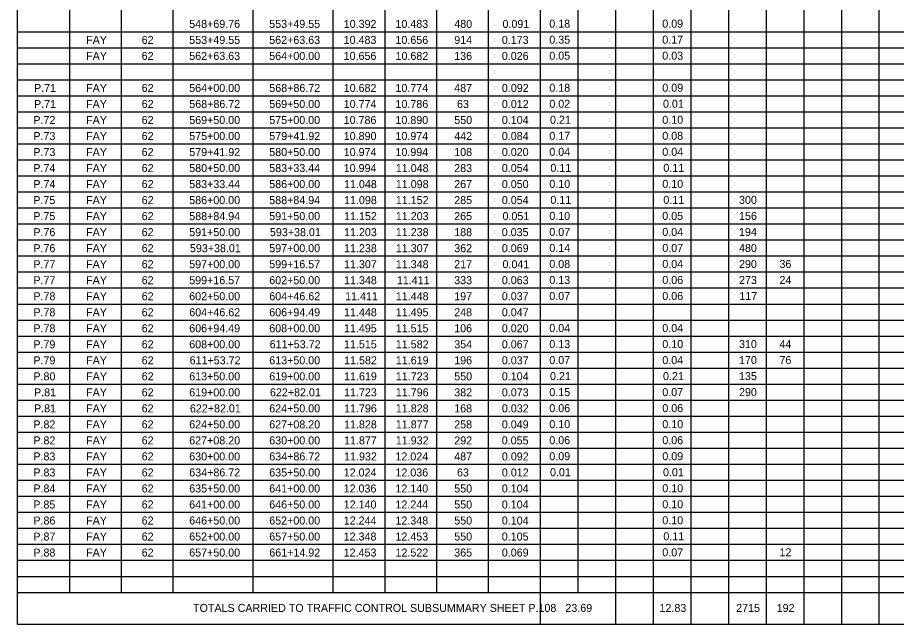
# Model space of a CAD drawing. Extents: x 12522 to 13018, y 1124 to 1902.
# Drawn here: x 12873.15 to 12888.52, y 1780.51 to 1791.12 of the extents above; entities that cross this region are included whole.
import ezdxf

# ---------------------------------------------------------------- set-up
doc = ezdxf.new("R2010")
doc.units = 0
for name, color, linetype in [('SC_Scratch1', 7, 'Continuous'), ('SH_Data', 7, 'Continuous'), ('SH_Text', 7, 'Continuous')]:
    doc.layers.add(name, color=color, linetype=linetype)

msp = doc.modelspace()

# ---------------------------------------------------------------- linework, layer by layer
at = {"layer": 'SC_Scratch1'}
msp.add_lwpolyline([(12873.148, 1801.509), (12903.648, 1801.509), (12903.648, 1780.509), (12873.148, 1780.509)], close=True, dxfattribs=at)
at = {"layer": 'SH_Data'}
for p, q in [((12882.289, 1801.509), (12882.289, 1780.525)), ((12875.865, 1800.949), (12875.865, 1781.069)), ((12877.265, 1800.949), (12877.265, 1781.069)), ((12878.665, 1800.949), (12878.665, 1781.069)), ((12879.571, 1800.949), (12879.571, 1781.069)), ((12880.477, 1800.949), (12880.477, 1781.069)), ((12881.383, 1800.949), (12881.383, 1781.069)), ((12883.607, 1800.949), (12883.607, 1780.525)), ((12884.265, 1800.949), (12884.265, 1780.525)), ((12884.924, 1800.949), (12884.924, 1780.525)), ((12885.583, 1800.949), (12885.583, 1780.525)), ((12886.242, 1800.949), (12886.242, 1780.525)), ((12886.901, 1800.949), (12886.901, 1780.525)), ((12887.56, 1800.949), (12887.56, 1780.525)), ((12888.218, 1800.949), (12888.218, 1780.525)), ((12882.948, 1798.709), (12882.948, 1781.069)), ((12874.054, 1797.589), (12874.054, 1781.069)), ((12874.96, 1797.589), (12874.96, 1781.069)), ((12873.148, 1790.869), (12903.668, 1790.869)), ((12873.148, 1790.589), (12903.668, 1790.589)), ((12873.148, 1790.309), (12903.668, 1790.309)), ((12873.148, 1790.029), (12903.668, 1790.029)), ((12873.148, 1789.749), (12903.668, 1789.749)), ((12873.148, 1789.469), (12903.668, 1789.469)), ((12873.148, 1789.189), (12903.668, 1789.189)), ((12873.148, 1788.909), (12903.668, 1788.909)), ((12873.148, 1788.629), (12903.668, 1788.629)), ((12873.148, 1788.349), (12903.668, 1788.349)), ((12873.148, 1788.069), (12903.668, 1788.069)), ((12873.148, 1787.789), (12903.668, 1787.789)), ((12873.148, 1787.509), (12903.668, 1787.509)), ((12873.148, 1787.229), (12903.668, 1787.229)), ((12873.148, 1786.949), (12903.668, 1786.949)), ((12873.148, 1786.669), (12903.668, 1786.669)), ((12873.148, 1786.389), (12903.668, 1786.389)), ((12873.148, 1786.109), (12903.668, 1786.109)), ((12873.148, 1785.829), (12903.668, 1785.829)), ((12873.148, 1785.549), (12903.668, 1785.549)), ((12873.148, 1785.269), (12903.668, 1785.269)), ((12873.148, 1784.989), (12903.668, 1784.989)), ((12873.148, 1784.709), (12903.668, 1784.709)), ((12873.148, 1784.429), (12903.668, 1784.429)), ((12873.148, 1784.149), (12903.668, 1784.149)), ((12873.148, 1783.869), (12903.668, 1783.869)), ((12873.148, 1783.589), (12903.668, 1783.589)), ((12873.148, 1783.309), (12903.668, 1783.309)), ((12873.148, 1783.029), (12903.668, 1783.029)), ((12873.148, 1782.749), (12903.668, 1782.749)), ((12873.148, 1782.469), (12903.668, 1782.469)), ((12873.148, 1782.189), (12903.668, 1782.189)), ((12873.148, 1781.909), (12903.668, 1781.909)), ((12873.148, 1781.629), (12903.668, 1781.629)), ((12873.148, 1781.349), (12903.668, 1781.349)), ((12873.148, 1781.069), (12903.668, 1781.069))]:
    msp.add_line(p, q, dxfattribs=at)

# ---------------------------------------------------------------- texts
at = {"layer": 'SH_Text'}
for s, p in [('548+69.76', (12876.151, 1790.935)), ('553+49.55', (12877.551, 1790.935)), ('10.392', (12878.854, 1790.935)), ('10.483', (12879.759, 1790.935)), ('480', (12880.788, 1790.935)), ('0.091', (12881.632, 1790.935)), ('0.18', (12882.451, 1790.939)), ('0.09', (12884.428, 1790.939)), ('FAY', (12874.347, 1790.655)), ('62', (12875.319, 1790.655)), ('553+49.55', (12876.151, 1790.655)), ('562+63.63', (12877.551, 1790.655)), ('10.483', (12878.853, 1790.655)), ('10.656', (12879.759, 1790.655)), ('914', (12880.788, 1790.655)), ('0.173', (12881.62, 1790.655)), ('0.35', (12882.451, 1790.659)), ('0.17', (12884.428, 1790.659)), ('FAY', (12874.347, 1790.375)), ('62', (12875.319, 1790.375)), ('562+63.63', (12876.151, 1790.375)), ('564+00.00', (12877.551, 1790.375)), ('10.656', (12878.853, 1790.375)), ('10.682', (12879.76, 1790.375)), ('136', (12880.787, 1790.375)), ('0.026', (12881.62, 1790.375)), ('0.05', (12882.451, 1790.379)), ('0.03', (12884.428, 1790.379)), ('P.71', (12873.436, 1789.815)), ('FAY', (12874.347, 1789.815)), ('62', (12875.319, 1789.815)), ('564+00.00', (12876.151, 1789.815)), ('568+86.72', (12877.552, 1789.815)), ('10.682', (12878.854, 1789.815)), ('10.774', (12879.759, 1789.815)), ('487', (12880.787, 1789.815)), ('0.092', (12881.621, 1789.815)), ('0.18', (12882.451, 1789.819)), ('0.09', (12884.428, 1789.819)), ('P.71', (12873.436, 1789.535)), ('FAY', (12874.347, 1789.535)), ('62', (12875.319, 1789.535)), ('568+86.72', (12876.152, 1789.535)), ('569+50.00', (12877.551, 1789.535)), ('10.774', (12878.854, 1789.535)), ('10.786', (12879.759, 1789.535)), ('63', (12880.836, 1789.535)), ('0.012', (12881.621, 1789.535)), ('0.02', (12882.452, 1789.539)), ('0.01', (12884.44, 1789.539)), ('P.72', (12873.424, 1789.255)), ('FAY', (12874.347, 1789.255)), ('62', (12875.319, 1789.255)), ('569+50.00', (12876.151, 1789.255)), ('575+00.00', (12877.551, 1789.255)), ('10.786', (12878.853, 1789.255)), ('10.890', (12879.759, 1789.255)), ('550', (12880.788, 1789.255)), ('0.104', (12881.62, 1789.255)), ('0.21', (12882.463, 1789.259)), ('0.10', (12884.428, 1789.259)), ('P.73', (12873.424, 1788.975)), ('FAY', (12874.347, 1788.975)), ('62', (12875.319, 1788.975)), ('575+00.00', (12876.151, 1788.975)), ('579+41.92', (12877.552, 1788.975)), ('10.890', (12878.854, 1788.975)), ('10.974', (12879.759, 1788.975)), ('442', (12880.788, 1788.975)), ('0.084', (12881.62, 1788.975)), ('0.17', (12882.451, 1788.979)), ('0.08', (12884.428, 1788.979)), ('P.73', (12873.424, 1788.695)), ('FAY', (12874.347, 1788.695)), ('62', (12875.319, 1788.695)), ('579+41.92', (12876.152, 1788.695)), ('580+50.00', (12877.551, 1788.695)), ('10.974', (12878.854, 1788.695)), ('10.994', (12879.759, 1788.695)), ('108', (12880.787, 1788.695)), ('0.020', (12881.62, 1788.695)), ('0.04', (12882.451, 1788.699)), ('0.04', (12884.428, 1788.699)), ('P.74', (12873.424, 1788.415)), ('FAY', (12874.347, 1788.415)), ('62', (12875.319, 1788.415)), ('580+50.00', (12876.151, 1788.415)), ('583+33.44', (12877.551, 1788.415)), ('10.994', (12878.854, 1788.415)), ('11.048', (12879.766, 1788.415)), ('283', (12880.787, 1788.415)), ('0.054', (12881.62, 1788.415)), ('0.11', (12882.47, 1788.419)), ('0.11', (12884.446, 1788.419)), ('P.74', (12873.424, 1788.135)), ('FAY', (12874.347, 1788.135)), ('62', (12875.319, 1788.135)), ('583+33.44', (12876.151, 1788.135)), ('586+00.00', (12877.551, 1788.135)), ('11.048', (12878.86, 1788.135)), ('11.098', (12879.766, 1788.135)), ('267', (12880.787, 1788.135)), ('0.050', (12881.62, 1788.135)), ('0.10', (12882.451, 1788.139)), ('0.10', (12884.428, 1788.139)), ('P.75', (12873.423, 1787.855)), ('FAY', (12874.347, 1787.855)), ('62', (12875.319, 1787.855)), ('586+00.00', (12876.151, 1787.855)), ('588+84.94', (12877.551, 1787.855)), ('11.098', (12878.86, 1787.855)), ('11.152', (12879.766, 1787.855)), ('285', (12880.787, 1787.855)), ('0.054', (12881.62, 1787.855)), ('0.11', (12882.47, 1787.859)), ('0.11', (12884.446, 1787.859)), ('300', (12885.77, 1787.859)), ('P.75', (12873.423, 1787.575)), ('FAY', (12874.347, 1787.575)), ('62', (12875.319, 1787.575)), ('588+84.94', (12876.151, 1787.575)), ('591+50.00', (12877.551, 1787.575)), ('11.152', (12878.861, 1787.575)), ('11.203', (12879.766, 1787.575)), ('265', (12880.787, 1787.575)), ('0.051', (12881.632, 1787.575)), ('0.10', (12882.451, 1787.579)), ('0.05', (12884.427, 1787.579)), ('156', (12885.77, 1787.579)), ('P.76', (12873.424, 1787.295)), ('62', (12875.319, 1787.295)), ('591+50.00', (12876.151, 1787.295)), ('593+38.01', (12877.563, 1787.295)), ('11.203', (12878.86, 1787.295)), ('11.238', (12879.766, 1787.295)), ('188', (12880.787, 1787.295)), ('0.035', (12881.619, 1787.295)), ('0.07', (12882.451, 1787.299)), ('0.04', (12884.428, 1787.299)), ('194', (12885.77, 1787.299)), ('FAY', (12874.347, 1787.295)), ('P.76', (12873.424, 1787.015)), ('FAY', (12874.347, 1787.015)), ('62', (12875.319, 1787.015)), ('593+38.01', (12876.163, 1787.015)), ('597+00.00', (12877.551, 1787.015)), ('11.238', (12878.86, 1787.015)), ('11.307', (12879.766, 1787.015)), ('362', (12880.788, 1787.015)), ('0.069', (12881.62, 1787.015)), ('0.14', (12882.451, 1787.019)), ('0.07', (12884.428, 1787.019)), ('480', (12885.77, 1787.019)), ('P.77', (12873.424, 1786.735)), ('FAY', (12874.347, 1786.735)), ('62', (12875.319, 1786.735)), ('597+00.00', (12876.151, 1786.735)), ('599+16.57', (12877.551, 1786.735)), ('11.307', (12878.86, 1786.735)), ('11.348', (12879.766, 1786.735)), ('217', (12880.787, 1786.735)), ('0.041', (12881.632, 1786.735)), ('0.08', (12882.451, 1786.739)), ('0.04', (12884.428, 1786.739)), ('290', (12885.77, 1786.739)), ('36', (12886.477, 1786.739)), ('P.77', (12873.424, 1786.455)), ('FAY', (12874.347, 1786.455)), ('62', (12875.319, 1786.455)), ('599+16.57', (12876.151, 1786.455)), ('602+50.00', (12877.551, 1786.455)), ('11.348', (12878.86, 1786.455)), ('11.411', (12879.784, 1786.455)), ('333', (12880.787, 1786.455)), ('0.063', (12881.62, 1786.455)), ('0.13', (12882.451, 1786.459)), ('0.06', (12884.428, 1786.459)), ('273', (12885.77, 1786.459)), ('24', (12886.478, 1786.459)), ('P.78', (12873.424, 1786.175)), ('FAY', (12874.347, 1786.175)), ('62', (12875.319, 1786.175)), ('602+50.00', (12876.151, 1786.175)), ('604+46.62', (12877.552, 1786.175)), ('11.411', (12878.879, 1786.175)), ('11.448', (12879.766, 1786.175)), ('197', (12880.787, 1786.175)), ('0.037', (12881.62, 1786.175)), ('0.07', (12882.451, 1786.179)), ('0.06', (12884.428, 1786.179)), ('117', (12885.776, 1786.179)), ('P.78', (12873.424, 1785.895)), ('FAY', (12874.347, 1785.895)), ('62', (12875.319, 1785.895)), ('604+46.62', (12876.152, 1785.895)), ('606+94.49', (12877.551, 1785.895)), ('11.448', (12878.86, 1785.895)), ('11.495', (12879.765, 1785.895)), ('248', (12880.787, 1785.895)), ('0.047', (12881.62, 1785.895)), ('P.78', (12873.424, 1785.615)), ('FAY', (12874.347, 1785.615)), ('62', (12875.319, 1785.615)), ('606+94.49', (12876.151, 1785.615)), ('608+00.00', (12877.551, 1785.615)), ('11.495', (12878.859, 1785.615)), ('11.515', (12879.765, 1785.615)), ('106', (12880.787, 1785.615)), ('0.020', (12881.62, 1785.615)), ('0.04', (12882.451, 1785.619)), ('0.04', (12884.428, 1785.619)), ('P.79', (12873.424, 1785.335)), ('FAY', (12874.347, 1785.335)), ('62', (12875.319, 1785.335)), ('608+00.00', (12876.151, 1785.335)), ('611+53.72', (12877.558, 1785.335)), ('11.515', (12878.859, 1785.335)), ('11.582', (12879.766, 1785.335)), ('354', (12880.788, 1785.335)), ('0.067', (12881.62, 1785.335)), ('0.13', (12882.451, 1785.339)), ('0.10', (12884.428, 1785.339)), ('310', (12885.77, 1785.339)), ('44', (12886.478, 1785.339)), ('P.79', (12873.424, 1785.055)), ('FAY', (12874.347, 1785.055)), ('62', (12875.319, 1785.055)), ('611+53.72', (12876.158, 1785.055)), ('613+50.00', (12877.551, 1785.055)), ('11.582', (12878.861, 1785.055)), ('11.619', (12879.766, 1785.055)), ('196', (12880.787, 1785.055)), ('0.037', (12881.62, 1785.055)), ('0.07', (12882.451, 1785.059)), ('0.04', (12884.428, 1785.059)), ('170', (12885.77, 1785.059)), ('76', (12886.477, 1785.059)), ('P.80', (12873.424, 1784.775)), ('FAY', (12874.347, 1784.775)), ('62', (12875.319, 1784.775)), ('613+50.00', (12876.151, 1784.775)), ('619+00.00', (12877.551, 1784.775)), ('11.619', (12878.86, 1784.775)), ('11.723', (12879.766, 1784.775)), ('550', (12880.788, 1784.775)), ('0.104', (12881.62, 1784.775)), ('0.21', (12882.463, 1784.779)), ('0.21', (12884.44, 1784.779)), ('135', (12885.769, 1784.779)), ('P.81', (12873.436, 1784.495)), ('FAY', (12874.347, 1784.495)), ('62', (12875.319, 1784.495)), ('619+00.00', (12876.151, 1784.495)), ('622+82.01', (12877.563, 1784.495)), ('11.723', (12878.86, 1784.495)), ('11.796', (12879.766, 1784.495)), ('382', (12880.788, 1784.495)), ('0.073', (12881.62, 1784.495)), ('0.15', (12882.451, 1784.499)), ('0.07', (12884.428, 1784.499)), ('290', (12885.77, 1784.499)), ('P.81', (12873.436, 1784.215)), ('FAY', (12874.347, 1784.215)), ('62', (12875.319, 1784.215)), ('622+82.01', (12876.163, 1784.215)), ('624+50.00', (12877.551, 1784.215)), ('11.796', (12878.86, 1784.215)), ('11.828', (12879.766, 1784.215)), ('168', (12880.787, 1784.215)), ('0.032', (12881.621, 1784.215)), ('0.06', (12882.451, 1784.219)), ('0.06', (12884.428, 1784.219)), ('P.82', (12873.424, 1783.935)), ('FAY', (12874.347, 1783.935)), ('62', (12875.319, 1783.935)), ('624+50.00', (12876.151, 1783.935)), ('627+08.20', (12877.551, 1783.935)), ('11.828', (12878.86, 1783.935)), ('11.877', (12879.766, 1783.935)), ('258', (12880.787, 1783.935)), ('0.049', (12881.62, 1783.935)), ('0.10', (12882.451, 1783.939)), ('0.10', (12884.428, 1783.939)), ('P.82', (12873.424, 1783.655)), ('FAY', (12874.347, 1783.655)), ('62', (12875.319, 1783.655)), ('627+08.20', (12876.151, 1783.655)), ('630+00.00', (12877.551, 1783.655)), ('11.877', (12878.86, 1783.655)), ('11.932', (12879.766, 1783.655)), ('292', (12880.788, 1783.655)), ('0.055', (12881.619, 1783.655)), ('0.06', (12882.451, 1783.659)), ('0.06', (12884.428, 1783.659)), ('P.83', (12873.424, 1783.375)), ('FAY', (12874.347, 1783.375)), ('62', (12875.319, 1783.375)), ('630+00.00', (12876.151, 1783.375)), ('634+86.72', (12877.552, 1783.375)), ('11.932', (12878.861, 1783.375)), ('12.024', (12879.759, 1783.375)), ('487', (12880.787, 1783.375)), ('0.092', (12881.621, 1783.375)), ('0.09', (12882.451, 1783.379)), ('0.09', (12884.428, 1783.379)), ('P.83', (12873.424, 1783.095)), ('FAY', (12874.347, 1783.095)), ('62', (12875.319, 1783.095)), ('634+86.72', (12876.152, 1783.095)), ('635+50.00', (12877.551, 1783.095)), ('12.024', (12878.854, 1783.095)), ('12.036', (12879.759, 1783.095)), ('63', (12880.836, 1783.095)), ('0.012', (12881.621, 1783.095)), ('0.01', (12882.463, 1783.099)), ('0.01', (12884.44, 1783.099)), ('P.84', (12873.424, 1782.815)), ('FAY', (12874.347, 1782.815)), ('62', (12875.319, 1782.815)), ('635+50.00', (12876.151, 1782.815)), ('641+00.00', (12877.551, 1782.815)), ('12.036', (12878.853, 1782.815)), ('12.140', (12879.759, 1782.815)), ('550', (12880.788, 1782.815)), ('0.104', (12881.62, 1782.815)), ('0.10', (12884.428, 1782.819)), ('P.85', (12873.423, 1782.535)), ('FAY', (12874.347, 1782.535)), ('62', (12875.319, 1782.535)), ('641+00.00', (12876.151, 1782.535)), ('646+50.00', (12877.551, 1782.535)), ('12.140', (12878.854, 1782.535)), ('12.244', (12879.759, 1782.535)), ('550', (12880.788, 1782.535)), ('0.104', (12881.62, 1782.535)), ('0.10', (12884.428, 1782.539)), ('P.86', (12873.424, 1782.255)), ('FAY', (12874.347, 1782.255)), ('62', (12875.319, 1782.255)), ('646+50.00', (12876.151, 1782.255)), ('652+00.00', (12877.551, 1782.255)), ('12.244', (12878.854, 1782.255)), ('12.348', (12879.759, 1782.255)), ('550', (12880.788, 1782.255)), ('0.104', (12881.62, 1782.255)), ('0.10', (12884.428, 1782.259)), ('P.87', (12873.424, 1781.975)), ('FAY', (12874.347, 1781.975)), ('62', (12875.319, 1781.975)), ('652+00.00', (12876.151, 1781.975)), ('657+50.00', (12877.551, 1781.975)), ('12.348', (12878.853, 1781.975)), ('12.453', (12879.759, 1781.975)), ('550', (12880.788, 1781.975)), ('0.105', (12881.619, 1781.975)), ('0.11', (12884.446, 1781.979)), ('P.88', (12873.424, 1781.695)), ('FAY', (12874.347, 1781.695)), ('62', (12875.319, 1781.695)), ('657+50.00', (12876.151, 1781.695)), ('661+14.92', (12877.552, 1781.695)), ('12.453', (12878.853, 1781.695)), ('12.522', (12879.76, 1781.695)), ('365', (12880.787, 1781.695)), ('0.069', (12881.62, 1781.695)), ('0.07', (12884.428, 1781.699)), ('12', (12886.478, 1781.699)), ('TOTALS CARRIED TO TRAFFIC CONTROL SUBSUMMARY SHEET P.108', (12876.218, 1780.727)), ('23.69', (12882.732, 1780.727)), ('12.83', (12884.379, 1780.727)), ('2715', (12885.72, 1780.727)), ('192', (12886.429, 1780.727))]:
    msp.add_text(s, height=0.14, dxfattribs=at).set_placement(p)

doc.saveas('drawing.dxf')
